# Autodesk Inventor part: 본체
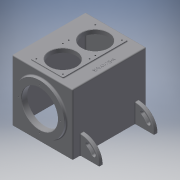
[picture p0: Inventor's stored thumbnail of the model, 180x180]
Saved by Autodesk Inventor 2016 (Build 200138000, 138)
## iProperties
Created: 2016-11
Part Number: 본체
Material: 알루미늄 6061
Document SubType Name: Modeling
Designer: mduedu
Density: 2.71 g/cm^3
Appearance: 기본값
Mass: 2889.02 g
Surface Area: 2673.51 cm^2
Volume: 1066.06 cm^3
Author: mduedu
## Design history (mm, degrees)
sketch "스케치1"
  geometry: L1 (-80, 0)-(80, 0); L2 (80, 0)-(80, 160); L3 (80, 160)-(-80, 160); L4 (-80, 160)-(-80, 0); 2 further points
  constraints: 8 end point, 2 parallel, 1 coincident, 1 horizontal, 1 midpoint, 1 perpendicular
  dimensions: "d0" = 160 distance of L2.end L3.end; "d2" = 160 distance of L1.end L2.end
extrude "돌출1" new body sketch "스케치1" stored distance "d3" = 194; taper "d4" = 0 deg
sketch "스케치4"
  geometry: L1 (80, 160)-(-80, 160) reference; L2 (-80, 160)-(-80, 0) reference; L3 (80, 0)-(80, 160) reference; L4 (-72, 0)-(-72, 152); L5 (-72, 152)-(72, 152); L6 (72, 152)-(72, 0); L7 (-72, 0)-(72, 0); 4 further points
  constraints: 8 end point, 1 coincident, 1 midpoint, 1 perpendicular
  dimensions: "d23" = 8 distance between parallel lines of L5 L1; "d24" = 8 distance between parallel lines of L3 L6 (= d23); "d25" = 8 distance between parallel lines of L2 L4 (= d23)
extrude "돌출4" cut sketch "스케치4" stored distance "d26" = 178; taper "d27" = 0 deg
fillet "모깎기5" dims "d28" = 3
fillet "모깎기6" dims "d29" = 3
fillet "모깎기7" dims "d30" = 3
fillet "모깎기8" dims "d31" = 3
sketch "스케치5"
  geometry: C1 r 65 at (0, 80); 1 further point
  constraints: 1 centre point, 1 vertical alignment
  dimensions: "d32" = 130 diameter of C1; "d33" = 80 distance of C1.centre point (0, 0)
extrude "돌출5" join sketch "스케치5" distance "d34" = 7; taper "d35" = 0 deg
sketch "스케치6"
  geometry: L1 (0, -3)-(154, -3) reference; L2 (154, 191)-(0, 191) reference; C1 r 35 at (77, 51.5); C2 r 35 at (77, 136.5); 2 further points
  constraints: 2 centre point, 2 vertical alignment, 1 coincident
  dimensions: "d36" = 70 diameter of C1; "d100" = 54.5 distance from line of point (77, 51.5) L1; "d101" = 70 diameter of C2; "d102" = 54.5 distance from line of C2.centre L2
extrude "돌출6" cut sketch "스케치6" stored distance "d37" = 7; taper "d38" = 0 deg
sketch "스케치7"
  geometry: L1 (34.5, 9)-(119.5, 9); L2 (119.5, 9)-(119.5, 179); L3 (119.5, 179)-(34.5, 179); L4 (34.5, 179)-(34.5, 9); L5 (0, -3)-(154, -3) reference; L6 (154, 191)-(0, 191) reference; C1 r 35 at (77, 51.5) reference; C2 r 35 at (77, 136.5) reference; 2 further points
  constraints: 8 end point, 2 parallel, 1 horizontal, 1 midpoint, 1 perpendicular, 1 vertical alignment
  dimensions: "d95" = 170 distance of L3.end L1.start; "d97" = 85 distance of L1.start L1.end; "d98" = 12 distance between parallel lines of L1 L5; "d99" = 12 distance between parallel lines of L3 L6 (derived)
extrude "돌출7" join sketch "스케치7" distance "d41" = 3; taper "d42" = 0 deg
fillet "모깎기9" dims "d43" = 3
fillet "모깎기10" dims "d44" = 2
hole "구멍2" diameter "d47" = 95; stored, may be unused: countersink angle "d51" = 90 deg, drill point angle "d53" = 118 deg; dims "d45" = 10, "d46" = 10, "d48" = 6, "d49" = 14, "d50" = 8, "d52" = 8
chamfer "모따기1" distance "d54" = 1; stored, may be unused: second distance "d55" = 2, angle "d56" = 45 deg
sketch "스케치8"
  geometry: C1 r 65 at (0, 80) reference; C2 r 31.5 at (0, 80); 1 further point
  constraints: 1 centre point, 1 coincident
  dimensions: "d57" = 63 diameter of C2
extrude "돌출8" join sketch "스케치8" distance "d58" = 14; taper "d59" = 0 deg
hole "구멍3" diameter "d62" = 30; stored, may be unused: countersink angle "d66" = 90 deg, drill point angle "d68" = 0 deg; dims "d60" = 10, "d61" = 10, "d63" = 6, "d64" = 47, "d65" = 14, "d67" = 17
fillet "모깎기11" dims "d69" = 3
fillet "모깎기12" dims "d70" = 3
fillet "모깎기13" dims "d71" = 0.5
chamfer "모따기2" distance "d72" = 1; stored, may be unused: second distance "d73" = 2, angle "d74" = 45 deg
fillet "모깎기14" dims "d75" = 3
sketch "스케치9"
  geometry: L1 (157, 0)-(157, 188) reference; L2 (77, 94)-(157, 94); 1 further point
  constraints: 2 end point, 1 midpoint, 1 point on line, 1 other
  dimensions: "d78" = 65 distance of point (142, 94) L2.start
feature "엠보싱1" sketch "스케치9" dims "d79" = 0.5, "d80" = 0
sketch "스케치10"
  geometry: 4 further points
  constraints: 4 other
hole "구멍4" sketch "스케치10" at (0, -55), (55, 0), (-55, 0), (0, 55) diameter "d81" = 3.242; stored, may be unused: countersink angle "d85" = 90 deg, drill point angle "d87" = 120 deg; dims "d82" = 6.6, "d83" = 4, "d84" = 2, "d86" = 8.6
sketch "스케치11"
  geometry: L1 (189, 94)-(-35, 94) reference; 8 further points
  constraints: 4 symmetric about line, 4 other
hole "구멍5" sketch "스케치11" at (42, 86.5), (112, 86.5), (112, 16.5), (42, 16.5), (42, 101.5), (112, 101.5), (112, 171.5), (42, 171.5) diameter "d88" = 3.242; stored, may be unused: countersink angle "d92" = 90 deg, drill point angle "d94" = 120 deg; dims "d89" = 6.6, "d90" = 4, "d91" = 2, "d93" = 8.6
node "작업 평면1"
sketch "스케치12"
  geometry: L1 (80, 157)-(80, 0) reference; L2 (80, 50)-(80, 0); L3 (80, 0)-(130, 0); L4 (80, 0)-(123.301, 25); L5 (80, 0)-(105, 43.301); A1 r 50 centre (80, 0) between (130, 0) and (80, 50); A2 r 40 centre (80, 0) between (120, 0) and (80, 40); A3 r 5 centre (114.641, 20) between (110.311, 17.5) and (118.971, 22.5); A4 r 45 centre (80, 0) between (118.971, 22.5) and (102.5, 38.971); A5 r 35 centre (80, 0) between (110.311, 17.5) and (97.5, 30.311); A6 r 5 centre (100, 34.641) between (102.5, 38.971) and (97.5, 30.311); 1 further point
  constraints: 16 point on circle, 8 end point, 8 point on line, 6 centre point, 4 coincident, 1 collinear, 1 perpendicular, 1 vertical alignment
  dimensions: "d104" = 100 diameter of A1; "d105" = 40 radius of A2; "d106" = 30 deg angle of L3 L4; "d107" = 30 deg angle of L5 L1; "d109" = 10 diameter of A3
extrude "돌출9" join sketch "스케치12" distance "d110" = 10; taper "d111" = 0 deg
extrude "돌출10" cut sketch "스케치12" stored distance "d112" = 10; taper "d113" = 0 deg
fillet "모깎기15" dims "d114" = 2
fillet "모깎기16" dims "d115" = 2
chamfer "모따기3" distance "d116" = 1; stored, may be unused: second distance "d117" = 2, angle "d118" = 45 deg
node "솔리드1"
mirror "대칭4"
